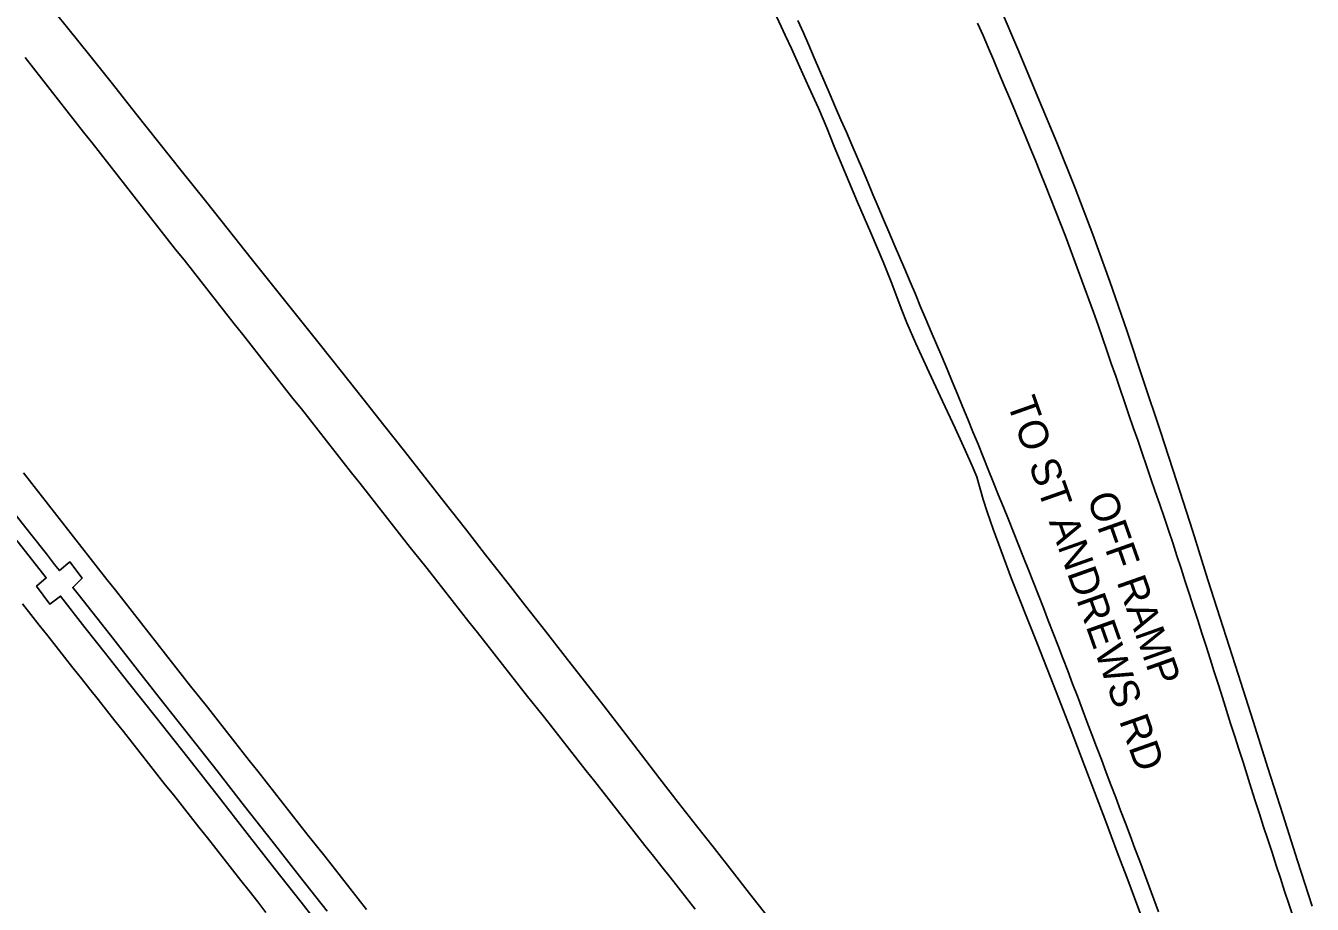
# Model space of a CAD drawing. Extents: x 1948091 to 1975253, y 787267 to 823306.
# Drawn here: x 1964618.7 to 1964856.2, y 804017.3 to 804179.4 of the extents above; entities that cross this region are included whole.
import ezdxf

# ---------------------------------------------------------------- set-up
doc = ezdxf.new("R2010")
doc.units = 0
for name, color, linetype in [('RD_EX_Pavement_Markings', 7, 'Continuous'), ('RD_EX_Road', 7, 'Continuous'), ('RD_TX_RoadID', 7, 'Continuous')]:
    doc.layers.add(name, color=color, linetype=linetype)

msp = doc.modelspace()

# ---------------------------------------------------------------- linework, layer by layer
at = {"layer": 'RD_EX_Pavement_Markings'}
for points in [[(1964761.26, 804180.38), (1964762.26, 804178.09), (1964763.25, 804175.8), (1964764.24, 804173.5), (1964765.24, 804171.21), (1964766.23, 804168.92), (1964767.22, 804166.62), (1964768.21, 804164.33), (1964769.2, 804162.04), (1964770.19, 804159.74), (1964771.19, 804157.45), (1964772.18, 804155.16), (1964773.16, 804152.86), (1964774.13, 804150.56), (1964775.11, 804148.26), (1964776.09, 804145.96), (1964777.07, 804143.66), (1964778.04, 804141.36), (1964779.02, 804139.06), (1964780, 804136.76), (1964780.97, 804134.46), (1964781.95, 804132.16), (1964782.93, 804129.86), (1964783.9, 804127.56), (1964784.88, 804125.25), (1964785.86, 804122.95), (1964786.83, 804120.65), (1964787.81, 804118.35), (1964788.79, 804116.05), (1964789.74, 804113.74), (1964790.69, 804111.43), (1964791.65, 804109.12), (1964792.6, 804106.81), (1964793.55, 804104.5), (1964794.5, 804102.18), (1964795.43, 804099.87), (1964796.37, 804097.55), (1964797.31, 804095.23), (1964798.24, 804092.91), (1964799.18, 804090.6), (1964800.11, 804088.28), (1964801.04, 804085.96), (1964801.97, 804083.63), (1964802.89, 804081.31), (1964803.82, 804078.99), (1964804.75, 804076.67), (1964805.66, 804074.34), (1964806.56, 804072.01), (1964807.47, 804069.68), (1964808.37, 804067.35), (1964809.28, 804065.02), (1964810.18, 804062.69), (1964811.07, 804060.35), (1964811.96, 804058.01), (1964812.84, 804055.68), (1964813.73, 804053.34), (1964814.61, 804051), (1964815.5, 804048.66), (1964816.39, 804046.33), (1964817.27, 804043.99), (1964818.16, 804041.65), (1964819.05, 804039.32), (1964819.94, 804036.98), (1964820.83, 804034.64), (1964821.71, 804032.3), (1964822.6, 804029.97), (1964823.48, 804027.63), (1964824.35, 804025.28), (1964825.22, 804022.94), (1964826.1, 804020.6), (1964826.97, 804018.26), (1964827.84, 804015.91)], [(1964794.43, 804179.87), (1964795.43, 804177.58), (1964796.41, 804175.28), (1964797.39, 804172.98), (1964798.36, 804170.68), (1964799.33, 804168.38), (1964800.31, 804166.08), (1964801.28, 804163.78), (1964802.24, 804161.47), (1964803.19, 804159.16), (1964804.15, 804156.85), (1964805.1, 804154.54), (1964806.04, 804152.22), (1964806.97, 804149.91), (1964807.91, 804147.59), (1964808.83, 804145.27), (1964809.73, 804142.93), (1964810.62, 804140.6), (1964811.5, 804138.26), (1964812.38, 804135.92), (1964813.25, 804133.58), (1964814.12, 804131.24), (1964814.98, 804128.89), (1964815.83, 804126.54), (1964816.66, 804124.18), (1964817.47, 804121.82), (1964818.29, 804119.46), (1964819.1, 804117.09), (1964819.92, 804114.73), (1964820.73, 804112.37), (1964821.54, 804110), (1964822.36, 804107.64), (1964823.17, 804105.28), (1964823.99, 804102.92), (1964824.8, 804100.55), (1964825.61, 804098.19), (1964826.43, 804095.83), (1964827.23, 804093.46), (1964828.04, 804091.09), (1964828.85, 804088.73), (1964829.66, 804086.36), (1964830.44, 804083.99), (1964831.22, 804081.61), (1964832, 804079.24), (1964832.77, 804076.86), (1964833.55, 804074.49), (1964834.31, 804072.11), (1964835.07, 804069.72), (1964835.84, 804067.34), (1964836.6, 804064.96), (1964837.36, 804062.58), (1964838.11, 804060.2), (1964838.87, 804057.82), (1964839.63, 804055.43), (1964840.39, 804053.05), (1964841.14, 804050.67), (1964841.9, 804048.29), (1964842.66, 804045.9), (1964843.42, 804043.52), (1964844.18, 804041.14), (1964844.94, 804038.76), (1964845.69, 804036.38), (1964846.45, 804033.99), (1964847.23, 804031.62), (1964848, 804029.24), (1964848.78, 804026.86), (1964849.55, 804024.49), (1964850.33, 804022.11), (1964851.11, 804019.74), (1964851.89, 804017.36), (1964852.67, 804014.99)], [(1964618.56, 804173.52), (1964620.11, 804171.55), (1964621.66, 804169.59), (1964623.2, 804167.63), (1964624.75, 804165.66), (1964626.29, 804163.7), (1964627.84, 804161.73), (1964629.38, 804159.76), (1964630.93, 804157.8), (1964632.47, 804155.83), (1964634.01, 804153.87), (1964635.56, 804151.9), (1964637.1, 804149.93), (1964638.65, 804147.97), (1964640.19, 804146), (1964641.74, 804144.04), (1964643.28, 804142.07), (1964644.82, 804140.1), (1964646.37, 804138.14), (1964647.92, 804136.18), (1964649.47, 804134.21), (1964651.01, 804132.25), (1964652.56, 804130.29), (1964654.11, 804128.32), (1964655.65, 804126.36), (1964657.2, 804124.39), (1964658.75, 804122.43), (1964660.3, 804120.47), (1964661.84, 804118.5), (1964663.39, 804116.54), (1964664.94, 804114.58), (1964666.48, 804112.61), (1964668.03, 804110.65), (1964669.58, 804108.69), (1964671.13, 804106.72), (1964672.67, 804104.76), (1964674.22, 804102.79), (1964675.77, 804100.83), (1964677.32, 804098.87), (1964678.86, 804096.9), (1964680.41, 804094.94), (1964681.96, 804092.98), (1964683.5, 804091.01), (1964685.05, 804089.05), (1964686.6, 804087.09), (1964688.15, 804085.12), (1964689.69, 804083.16), (1964691.24, 804081.19), (1964692.79, 804079.23), (1964694.33, 804077.27), (1964695.88, 804075.3), (1964697.43, 804073.34), (1964698.98, 804071.38), (1964700.52, 804069.41), (1964702.07, 804067.45), (1964703.62, 804065.48), (1964705.16, 804063.52), (1964706.71, 804061.56), (1964708.26, 804059.59), (1964709.81, 804057.63), (1964711.35, 804055.67), (1964712.9, 804053.7), (1964714.45, 804051.74), (1964715.99, 804049.77), (1964717.54, 804047.81), (1964719.09, 804045.85), (1964720.63, 804043.88), (1964722.18, 804041.92), (1964723.73, 804039.96), (1964725.28, 804037.99), (1964726.82, 804036.03), (1964728.37, 804034.06), (1964729.92, 804032.1), (1964731.46, 804030.14), (1964733.01, 804028.17), (1964734.56, 804026.21), (1964736.1, 804024.24), (1964737.65, 804022.28), (1964739.2, 804020.32), (1964740.75, 804018.35), (1964742.29, 804016.39)], [(1964618.25, 804096.9), (1964619.8, 804094.93), (1964621.34, 804092.97), (1964622.89, 804091), (1964624.43, 804089.04), (1964625.97, 804087.07), (1964627.52, 804085.1), (1964629.06, 804083.14), (1964630.6, 804081.17), (1964632.15, 804079.2), (1964633.69, 804077.24), (1964635.24, 804075.27), (1964636.78, 804073.3), (1964638.32, 804071.34), (1964639.87, 804069.37), (1964641.41, 804067.4), (1964642.95, 804065.44), (1964644.5, 804063.47), (1964646.04, 804061.5), (1964647.59, 804059.54), (1964649.13, 804057.58), (1964650.68, 804055.61), (1964652.23, 804053.65), (1964653.77, 804051.68), (1964655.32, 804049.72), (1964656.87, 804047.76), (1964658.41, 804045.79), (1964659.96, 804043.83), (1964661.51, 804041.86), (1964663.05, 804039.9), (1964664.6, 804037.93), (1964666.15, 804035.97), (1964667.69, 804034.01), (1964669.24, 804032.04), (1964670.79, 804030.08), (1964672.34, 804028.12), (1964673.89, 804026.16), (1964675.44, 804024.19), (1964676.99, 804022.23), (1964678.53, 804020.27), (1964680.08, 804018.31), (1964681.63, 804016.34)], [(1964618.11, 804072.72), (1964619.65, 804070.75), (1964621.2, 804068.79), (1964622.76, 804066.83), (1964624.31, 804064.87), (1964625.86, 804062.91), (1964627.41, 804060.94), (1964628.96, 804058.98), (1964630.51, 804057.02), (1964632.06, 804055.06), (1964633.61, 804053.1), (1964635.16, 804051.14), (1964636.71, 804049.18), (1964638.26, 804047.22), (1964639.81, 804045.26), (1964641.36, 804043.3), (1964642.91, 804041.33), (1964644.46, 804039.37), (1964646.01, 804037.41), (1964647.56, 804035.45), (1964649.11, 804033.49), (1964650.66, 804031.53), (1964652.22, 804029.57), (1964653.77, 804027.61), (1964655.32, 804025.65), (1964656.87, 804023.68), (1964658.42, 804021.72), (1964659.97, 804019.76), (1964661.51, 804017.79), (1964663.04, 804015.82)]]:
    msp.add_lwpolyline(points, dxfattribs=at)
at = {"layer": 'RD_EX_Road'}
for points in [[(1964755.49, 804015.24), (1964752.32, 804019.28), (1964749.1, 804023.39), (1964745.82, 804027.57), (1964742.51, 804031.81), (1964739.16, 804036.11), (1964735.78, 804040.48), (1964732.36, 804044.91), (1964728.9, 804049.39), (1964725.39, 804053.9), (1964721.85, 804058.46), (1964718.25, 804063.05), (1964714.63, 804067.68), (1964710.97, 804072.35), (1964707.3, 804077.06), (1964703.59, 804081.81), (1964699.87, 804086.57), (1964696.14, 804091.34), (1964692.39, 804096.11), (1964688.64, 804100.88), (1964684.83, 804105.7), (1964680.93, 804110.63), (1964676.93, 804115.66), (1964672.84, 804120.79), (1964668.69, 804125.99), (1964664.52, 804131.22), (1964660.32, 804136.48), (1964656.1, 804141.77), (1964651.86, 804147.1), (1964647.58, 804152.46), (1964643.29, 804157.85), (1964638.96, 804163.29), (1964634.68, 804168.66), (1964630.51, 804173.88), (1964626.44, 804178.94), (1964622.48, 804183.84)], [(1964856.21, 804016.96), (1964853.51, 804025.32), (1964850.77, 804033.9), (1964848.02, 804042.51), (1964845.28, 804051.12), (1964842.52, 804059.74), (1964839.74, 804068.39), (1964836.95, 804077.16), (1964834.13, 804086.09), (1964831.21, 804095.22), (1964828.16, 804104.54), (1964825.08, 804113.88), (1964821.98, 804123.18), (1964818.86, 804132.19), (1964815.72, 804140.9), (1964812.44, 804149.43), (1964809.03, 804157.83), (1964805.55, 804166.23), (1964802.01, 804174.67), (1964798.42, 804183.15)], [(1964757.31, 804181.12), (1964758.15, 804179.28), (1964758.91, 804177.66), (1964760.04, 804175.18), (1964761.59, 804171.78), (1964763.28, 804168.06), (1964765.02, 804164.18), (1964766.57, 804160.58), (1964767.97, 804157.1), (1964769.86, 804152.54), (1964772.27, 804146.87), (1964774.7, 804141.19), (1964776.97, 804135.85), (1964778.61, 804131.86), (1964779.6, 804129.21), (1964780.45, 804126.92), (1964781.35, 804124.58), (1964783.04, 804120.76), (1964785.49, 804115.45), (1964787.97, 804110.12), (1964790.29, 804105.12), (1964792.13, 804101.12), (1964793.44, 804098.22), (1964794.27, 804096.17), (1964794.67, 804094.83), (1964795.04, 804093.5), (1964795.48, 804091.98), (1964796.21, 804089.69), (1964797.29, 804086.54), (1964798.76, 804082.5), (1964800.71, 804077.35), (1964803.61, 804069.93), (1964805.45, 804065.29), (1964808.93, 804056.48), (1964811.5, 804049.84), (1964814.2, 804042.75), (1964815.99, 804038.04), (1964818.07, 804032.56), (1964820.2, 804026.94), (1964822.14, 804021.81), (1964825.43, 804013.03)], [(1964614.38, 804092.26), (1964619.66, 804085.57), (1964622.5, 804081.96), (1964624.03, 804080.02), (1964624.94, 804078.86), (1964626.85, 804080.48), (1964629.13, 804077.5), (1964627.37, 804075.78), (1964628.34, 804074.54), (1964634.32, 804066.94), (1964639.32, 804060.59), (1964643.34, 804055.48), (1964648.93, 804048.38), (1964654.02, 804041.91), (1964659.1, 804035.44), (1964664.18, 804028.97), (1964669.26, 804022.51), (1964674.37, 804016.02)], [(1964617.06, 804084.4), (1964620.66, 804079.84), (1964622.48, 804077.53), (1964620.69, 804076.02), (1964623.16, 804072.66), (1964625.13, 804074.16), (1964629.6, 804068.39), (1964633.39, 804063.57), (1964637.45, 804058.44), (1964642.77, 804051.74), (1964648.59, 804044.37), (1964654.2, 804037.23), (1964659.56, 804030.39), (1964664.63, 804023.91), (1964669.53, 804017.67), (1964674.35, 804011.54)]]:
    msp.add_lwpolyline(points, dxfattribs=at)

# ---------------------------------------------------------------- texts
at = {"layer": 'RD_TX_RoadID'}
for s, p in [('TO ST ANDREWS RD', (1964799.8, 804109.85)), ('OFF RAMP', (1964814.57, 804092.34))]:
    msp.add_text(s, height=5.4, rotation=289.4445, dxfattribs=at).set_placement(p)

doc.saveas('drawing.dxf')
